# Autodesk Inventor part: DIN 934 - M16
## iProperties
Created: 2006-02
Part Number: DIN 934 - M16
Material: Steel, Mild
Description: Hex Nut
Document SubType Name: Modeling
Standard: DIN 934
Designer: Andy Moles
Standards Organization: DIN
Language: en-US
Size Designation: M16
Categories: <MemberInstance><Categories><Category DisplayName="Fasteners" InternalName="e4da775c-781d-43d5-af7c-5136215cf5a6" Mnemonic="FSTN"><Category DisplayName="Nuts" I
Density: 7.86 g/cm^3
Mass: 34.481 g
Surface Area: 21.9132 cm^2
Volume: 4.38689 cm^3
Author: Andy Moles
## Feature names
1. Body [Extrusion]
2. Chamfer1 [Revolution]
3. Thread [Hole]
4. Chamfer2
5. Chamfer3
